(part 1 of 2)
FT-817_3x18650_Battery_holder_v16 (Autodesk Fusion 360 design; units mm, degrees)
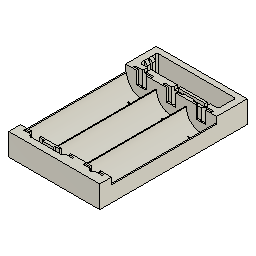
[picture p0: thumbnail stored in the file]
parameter "d153" = 1.5
parameter "d175" = 1.8
parameter "d203" = 3.15
parameter "d205" = 3
sketch "Sketch2" plane through (0, 0, 0) normal (0, 0, 1) x axis (1, 0, 0)
  line L1 (29, 41) -> (-29, 41)
  line L2 (29, -41) -> (29, 41)
  line L3 (-29, -41) -> (29, -41)
  line L4 (-29, 41) -> (-29, -41)
  line L5 (29, 53) -> (29, 41)
  line L6 (-29, 53) -> (29, 53)
  line L7 (-29, 41) -> (-29, 53)
  line L8 (0, -45) -> (0, 0)
  line L9 (-33, 0) -> (0, 0)
  point P1 (0, 0)
  point P8 (0, 0)
  point P10 (0, 0)
  point P4 (29, -41)
  point P6 (29, 53)
  point P5 (-29, -41)
  horizontal L1
  vertical L2
  horizontal L3
  vertical L4
  perpendicular L1 L5
  perpendicular L5 L6
  perpendicular L1 L7
  coincident P1 P8
  vertical L8
  coincident P1 P10
  perpendicular L4 L9
  symmetric L2 L4 L8
  symmetric L1 L3 L9
  dimension "d9" distance P4 P6 = 94
  dimension "d10" distance P4 P5 = 58
  dimension "d27" distance L3 L9 = 41
extrude "Extrude2" new body sketch "Sketch2" profile of L1 L2 L3 L4 L5 L6 L7 along normal blind 14.2
sketch "18650" plane through (0, 0, 0) normal (0, 1, 0) x axis (1, 0, 0)
  line L1 (0, -22) -> (0, 0)
  line L2 (56, -0.2) -> (-41, -0.2)
  line L3 (85, 0) -> (0, 0)
  line L4 (-9.75, -26.6294) -> (-9.75, 2.3706)
  line L5 (-9.25, -26.6294) -> (-9.25, 1.9073)
  line L6 (9.25, -26) -> (9.25, 2)
  line L7 (9.75, -25.722) -> (9.75, 2.278)
  circle C1 centre (0, -9.45) radius 9.25
  circle C2 centre (19, -9.45) radius 9.25
  circle C3 centre (-19, -9.45) radius 9.25
  point P1 (0, 0)
  point P2 (0, 0)
  point P4 (0, -9.45)
  point P7 (0, 0)
  coincident P1 P2
  vertical L1
  coincident L1 P4
  horizontal L2
  tangent C1 L2
  coincident P1 P7
  perpendicular L1 L3
  tangent L2 C2
  tangent L2 C3
  perpendicular L2 L4
  perpendicular L2 L5
  tangent C3 L4
  tangent C1 L5
  perpendicular L2 L6
  perpendicular L3 L7
  tangent C2 L7
  tangent C1 L6
  dimension "d1" diameter C1 = 18.5
  dimension "d2" distance L2 L3 = 0.2
  dimension "d3" diameter C2 = 18.5 (= "d1")
  dimension "d4" diameter C3 = 18.5 (= "d1")
  dimension "d5" distance L6 L7 = 0.5
  dimension "d6" distance L4 L5 = 0.5 (= "d5")
extrude "Extrude1" new body sketch "18650" profile of C1 C2 C3 distance 67 (= "70 mm - 3 mm") named "d7"
copy_paste_bodies "CopyPasteBodies1"
combine "Combine1"
sketch "Sketch3" plane through (-29, 0, 0) normal (-1, 0, 0) x axis (0, -1, 0)
  line L1 (41, 0) -> (-53, 0)
  line L2 (41, 14.2) -> (41, 0)
  line L3 (-53, 14.2) -> (41, 14.2)
  line L4 (-53, 0) -> (-53, 14.2)
  line L5 (-33.5, 10) -> (-33.5, 14.2)
  line L6 (33.5, 10) -> (-33.5, 10)
  line L7 (33.5, 14.2) -> (33.5, 10)
  line L8 (0, 23) -> (0, 0)
  line L9 (33.25, 14.2) -> (33.25, 10)
  point P6 (-33.5, 14.2)
  point P9 (33.5, 14.2)
  point P1 (0, 0)
  point P10 (0, 0)
  point P7 (-33.5, 10)
  point P8 (33.5, 10)
  coincident L3 P6
  perpendicular L3 L5
  perpendicular L5 L6
  coincident L3 P9
  perpendicular L3 L7
  coincident P1 P10
  perpendicular L6 L8
  symmetric L5 L7 L8
  dimension "d13" distance P6 P7 = 4.2
  dimension "d14" distance P7 P8 = 67 (= "d7")
  dimension "d18" = -0.25
sketch "Sketch4" plane through (0, 0, 14.2) normal (0, 0, 1) x axis (-1, 0, 0)
  line L1 (-29, -53) -> (-29, 41)
  line L2 (29, -53) -> (-29, -53)
  line L3 (29, 41) -> (29, -53)
  line L4 (-29, 41) -> (29, 41)
  line L5 (28.25, 0) -> (9.75, 0)
  line L6 (9.25, 0) -> (-9.25, 0)
  line L7 (-9.75, 0) -> (-28.25, 0)
  line L8 (19, -61.033) -> (19, 41.4982)
  line L9 (0, -61.033) -> (0, 41.8886)
  line L10 (-19, -60.5882) -> (-19, 42.3334)
  line L11 (-11.0627, 33.5) -> (-26.9373, 33.5)
  line L12 (-11.0627, -33.5) -> (-11.0627, 33.5)
  line L13 (-26.9373, -33.5) -> (-11.0627, -33.5)
  line L14 (-26.9373, 33.5) -> (-26.9373, -33.5)
  line L15 (7.9373, 33.5) -> (-7.9373, 33.5)
  line L16 (7.9373, -33.5) -> (7.9373, 33.5)
  line L17 (-7.9373, -33.5) -> (7.9373, -33.5)
  line L18 (-7.9373, 33.5) -> (-7.9373, -33.5)
  line L19 (26.9373, 33.5) -> (11.0627, 33.5)
  line L20 (26.9373, -33.5) -> (26.9373, 33.5)
  line L21 (11.0627, -33.5) -> (26.9373, -33.5)
  line L22 (11.0627, 33.5) -> (11.0627, -33.5)
  line L23 (6, 34.5) -> (-6, 34.5)
  line L24 (6, 35.5) -> (6, 34.5)
  line L25 (-6, 35.5) -> (6, 35.5)
  line L26 (-6, 34.5) -> (-6, 35.5)
  line L27 (3, 34.5) -> (3, 33.5)
  line L28 (-3, 34.5) -> (-3, 33.5)
  line L29 (-25, -44.6) -> (25, -44.6)
  line L30 (-25, -43.5) -> (-25, -44.6)
  line L31 (25, -43.5) -> (-25, -43.5)
  line L32 (25, -44.6) -> (25, -43.5)
  line L33 (-41.708, 0) -> (39.9599, 0)
  line L34 (-6, -35.5) -> (6, -35.5)
  line L35 (6, -35.5) -> (6, -34.5)
  line L36 (6, -34.5) -> (-6, -34.5)
  line L37 (-6, -34.5) -> (-6, -35.5)
  line L38 (-3, -34.5) -> (-3, -33.5)
  line L39 (3, -34.5) -> (3, -33.5)
  line L40 (-36.2069, -28.9904) -> (34.2527, -28.9904)
  line L41 (33.3168, 27.6224) -> (-72.3156, 27.6224)
  curve K1 (-16.2649, -28.9904) -> (-20.9089, -28.9904)
  curve K2 (-16.2649, -20.9904) -> (-16.2649, -28.9904)
  curve K3 (-20.9089, -20.9904) -> (-16.2649, -20.9904)
  curve K4 (-20.9089, -28.9904) -> (-20.9089, -20.9904)
  curve K5 (21.8796, -28.9904) -> (17.1621, -28.9904)
  curve K6 (21.8796, -20.9904) -> (21.8796, -28.9904)
  curve K7 (17.1621, -20.9904) -> (21.8796, -20.9904)
  curve K8 (17.1621, -28.9904) -> (17.1621, -20.9904)
  curve K9 (1.9562, -28.9904) -> (-0.9401, -28.9904)
  curve K10 (1.9562, -20.9904) -> (1.9562, -28.9904)
  curve K11 (-0.9401, -20.9904) -> (1.9562, -20.9904)
  curve K12 (-0.9401, -28.9904) -> (-0.9401, -20.9904)
  curve K13 (-3.5054, 27.6056) -> (1.7961, 27.6224)
  curve K14 (-3.48, 19.6057) -> (-3.5054, 27.6056)
  curve K15 (1.8215, 19.6225) -> (-3.48, 19.6057)
  curve K16 (1.7961, 27.6224) -> (1.8215, 19.6225)
  curve K17 (-22.211, 27.6224) -> (-18.0311, 27.6224)
  curve K18 (-22.211, 19.6224) -> (-22.211, 27.6224)
  curve K19 (-18.0311, 19.6224) -> (-22.211, 19.6224)
  curve K20 (-18.0311, 27.6224) -> (-18.0311, 19.6224)
  curve K21 (17.5387, 27.6188) -> (20.2052, 27.6224)
  curve K22 (17.5495, 19.6188) -> (17.5387, 27.6188)
  curve K23 (20.2161, 19.6224) -> (17.5495, 19.6188)
  curve K24 (20.2052, 27.6224) -> (20.2161, 19.6224)
  line L42 (25, -41.5) -> (-25, -41.5)
  line L43 (-25, -46.6) -> (25, -46.6)
  line L44 (23, -41.5) -> (23, -43.5)
  line L45 (23, -46.6) -> (23, -44.6)
  line L46 (-23, -41.5) -> (-23, -43.5)
  line L47 (-23, -44.6) -> (-23, -46.6)
  line L48 (-25, -49.6) -> (-25, -46.6)
  line L49 (25, -49.6) -> (-25, -49.6)
  line L50 (25, -49.6) -> (25, -46.6)
  line L51 (25, -38.5) -> (25, -41.5)
  line L52 (-25, -38.5) -> (25, -38.5)
  line L53 (-25, -41.5) -> (-25, -38.5)
  line L54 (12.5, -43.5) -> (12.5, -44.6)
  line L55 (23, -44.6) -> (23, -43.5)
  line L56 (-23, -44.6) -> (-23, -43.5)
  line L57 (14.3714, -49.6) -> (14.3714, -38.5)
  line L58 (10.6286, -49.6) -> (10.6286, -38.5)
  line L59 (-14.3714, -49.6) -> (-14.3714, -38.5)
  line L60 (-10.6286, -49.6) -> (-10.6286, -38.5)
  line L61 (-13, 34.5) -> (-25, 34.5)
  line L62 (-16, 34.5) -> (-16, 33.5)
  line L63 (-22, 34.5) -> (-22, 33.5)
  line L64 (-25, 34.5) -> (-25, 35.5)
  line L65 (-25, 35.5) -> (-13, 35.5)
  line L66 (-13, 35.5) -> (-13, 34.5)
  line L67 (-13, -34.5) -> (-25, -34.5)
  line L68 (-25, -35.5) -> (-13, -35.5)
  line L69 (-16, -34.5) -> (-16, -33.5)
  line L70 (-22, -34.5) -> (-22, -33.5)
  line L71 (-25, -34.5) -> (-25, -35.5)
  line L72 (-13, -35.5) -> (-13, -34.5)
  line L73 (25, 34.5) -> (13, 34.5)
  line L74 (22, 34.5) -> (22, 33.5)
  line L75 (16, 34.5) -> (16, 33.5)
  line L76 (13, 34.5) -> (13, 35.5)
  line L77 (13, 35.5) -> (25, 35.5)
  line L78 (25, 35.5) -> (25, 34.5)
  line L79 (25, -34.5) -> (13, -34.5)
  line L80 (13, -35.5) -> (25, -35.5)
  line L81 (22, -34.5) -> (22, -33.5)
  line L82 (16, -34.5) -> (16, -33.5)
  line L83 (13, -34.5) -> (13, -35.5)
  line L84 (25, -35.5) -> (25, -34.5)
  line L85 (0, 37) -> (19, 37)
  line L86 (-19, -37) -> (0, -37)
  line L87 (6, 35.5) -> (13, 35.5)
  line L88 (-13, -35.5) -> (-6, -35.5)
  line L89 (20, -38.5) -> (20, -36.618)
  line L90 (18, -38.5) -> (18, -36.618)
  line L91 (1, -38.5) -> (1, -36.618)
  line L92 (-1, -38.5) -> (-1, -36.618)
  line L93 (-18, -38.5) -> (-18, -36.618)
  line L94 (-20, -38.5) -> (-20, -36.618)
  circle C1 centre (0, 35.5) radius 1.5
  circle C2 centre (0, -35.5) radius 1.5
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  point P18 (19, 0)
  point P19 (0, 0)
  point P20 (-19, 0)
  point P37 (3, 33.5)
  point P38 (3, 34.5)
  point P39 (-3, 33.5)
  point P40 (-3, 34.5)
  point P41 (0, 35.5)
  point P1 (0, 0)
  point P33 (-6, 34.5)
  point P51 (-6, -34.5)
  point P34 (6, 34.5)
  point P50 (6, -34.5)
  point P35 (6, 35.5)
  point P48 (6, -35.5)
  point P36 (-6, 35.5)
  point P49 (-6, -35.5)
  point P54 (3, -33.5)
  point P55 (3, -34.5)
  point P52 (-3, -33.5)
  point P53 (-3, -34.5)
  point P61 (-20.9089, -28.9904)
  point P65 (17.1621, -28.9904)
  point P69 (-0.9401, -28.9904)
  point P73 (1.7961, 27.6224)
  point P83 (20.2052, 27.6224)
  point P77 (-18.0311, 27.6224)
  point P89 (23, -43.5)
  point P90 (23, -41.5)
  point P91 (23, -44.6)
  point P92 (23, -46.6)
  point P93 (-23, -43.5)
  point P94 (-23, -41.5)
  point P95 (-23, -46.6)
  point P96 (-23, -44.6)
  point P98 (25, -49.6)
  point P99 (25, -49.6)
  point P102 (12.5, -44.6)
  point P103 (12.5, -43.5)
  point P104 (14.3714, -38.5)
  point P108 (-14.3714, -38.5)
  point P105 (14.3714, -49.6)
  point P109 (-14.3714, -49.6)
  point P106 (10.6286, -38.5)
  point P110 (-10.6286, -38.5)
  point P107 (10.6286, -49.6)
  point P111 (-10.6286, -49.6)
  point P148 (19, 37)
  point P149 (0, 37)
  point P150 (0, -37)
  point P151 (-19, -37)
  point P153 (20, -38.5)
  point P155 (18, -38.5)
  point P156 (1, -36.618)
  point P157 (1, -38.5)
  point P158 (-1, -36.618)
  point P159 (-1, -38.5)
  point P161 (-18, -38.5)
  point P163 (-20, -38.5)
  point P42 (25, -44.6)
  point P43 (-25, -44.6)
  point P45 (25, -43.5)
  point P74 (-3.5054, 27.6056)
  point P75 (-3.48, 19.6057)
  point P66 (21.8796, -28.9904)
  point P67 (21.8796, -20.9904)
  point P62 (-16.2649, -28.9904)
  point P63 (-16.2649, -20.9904)
  point P72 (-0.9401, -20.9904)
  point P81 (20.2161, 19.6224)
  point P80 (-18.0311, 19.6224)
  point P44 (-25, -43.5)
  point P88 (-25, -46.6)
  point P97 (-25, -49.6)
  point P86 (25, -41.5)
  point P100 (25, -38.5)
  point P56 (0, -35.5)
  perpendicular L2 L8
  perpendicular L2 L9
  perpendicular L2 L10
  coincident L8 P18
  coincident L9 P19
  coincident L10 P20
  horizontal L23
  vertical L24
  horizontal L25
  vertical L26
  symmetric L9 L24 L26
  coincident L15 P37
  coincident L23 P38
  perpendicular L23 L27
  coincident L15 P39
  coincident L23 P40
  perpendicular L23 L28
  coincident L9 P41
  horizontal L29
  vertical L30
  horizontal L31
  vertical L32
  symmetric L9 L30 L32
  perpendicular L14 L33
  coincident P1 L33
  symmetric P33 L33 P51
  symmetric P34 L33 P50
  symmetric P35 L33 P48
  symmetric P36 L33 P49
  symmetric P37 L33 P54
  symmetric P38 L33 P55
  symmetric P39 L33 P52
  symmetric P40 L33 P53
  symmetric C1 L33 C2
  perpendicular K1 K2
  parallel K1 K3
  parallel K2 K4
  coincident L40 P61
  perpendicular K5 K6
  parallel K5 K7
  parallel K6 K8
  coincident L40 P65
  perpendicular K9 K10
  parallel K9 K11
  parallel K10 K12
  coincident L40 P69
  horizontal L41
  perpendicular K13 K14
  parallel K13 K15
  parallel K14 K16
  coincident L41 P73
  vertical K6
  vertical K10
  vertical K2
  horizontal L40
  perpendicular K17 K18
  parallel K17 K19
  parallel K18 K20
  perpendicular K21 K22
  parallel K21 K23
  parallel K22 K24
  coincident L41 P83
  coincident L41 P77
  coincident L31 P89
  coincident L42 P90
  perpendicular L42 L44
  coincident L29 P91
  coincident L43 P92
  perpendicular L43 L45
  coincident L31 P93
  coincident L42 P94
  perpendicular L42 L46
  coincident L43 P95
  coincident L29 P96
  perpendicular L29 L47
  perpendicular L43 L48
  perpendicular L48 L49
  perpendicular L43 L50
  coincident P98 P99
  perpendicular L42 L51
  perpendicular L10 L52
  perpendicular L42 L53
  coincident L29 P102
  coincident L31 P103
  perpendicular L31 L54
  perpendicular L43 L57
  perpendicular L43 L58
  symmetric L54 L57 L58
  symmetric L9 P104 P108
  symmetric L9 P105 P109
  symmetric L9 P106 P110
  symmetric L9 P107 P111
  coincident L52 P104
  coincident L49 P105
  coincident L49 P107
  coincident L52 P106
  coincident L25 P41
  coincident L8 P148
  coincident L9 P149
  coincident C1 P149
  coincident C2 P150
  coincident L9 P150
  coincident L10 P151
  coincident L52 P153
  perpendicular L52 L89
  coincident L52 P155
  perpendicular L52 L90
  coincident C2 P156
  coincident L52 P157
  perpendicular L52 L91
  coincident C2 P158
  coincident L52 P159
  perpendicular L52 L92
  coincident L52 P161
  perpendicular L52 L93
  coincident L52 P163
  perpendicular L52 L94
  symmetric L10 L93 L94
  dimension "d19" distance P33 P34 = 12
  dimension "d20" distance P33 P36 = 1
  dimension "d21" distance L27 L28 = 6
  dimension "d22" distance P37 P38 = 1
  dimension "d23" diameter C1 = 3
  dimension "d25" distance P42 P43 = 50
  dimension "d26" distance P42 P45 = 1.1
  dimension "d42" distance P74 P75 = 8
  dimension "d43" distance P66 P67 = 8 (= "d42")
  dimension "d44" distance P62 P63 = 8 (= "d42")
  dimension "d45" distance P69 P72 = 8 (= "d42")
  dimension "d46" distance P81 P83 = 8 (= "d42")
  dimension "d47" distance P77 P80 = 8 (= "d42")
  dimension "d52" = -2
  dimension "d53" = -2
  dimension "d54" distance P42 P91 = 2
  dimension "d55" distance P45 P89 = 2 (= "d54")
  dimension "d56" distance P43 P96 = 2 (= "d54")
  dimension "d57" distance P44 P93 = 2 (= "d54")
  dimension "d58" distance P88 P97 = 3
  dimension "d59" distance P86 P100 = 3
  dimension "d61" distance P56 L52 = 3
  dimension "d63" distance L9 L54 = 12.5 (= "( d25 / 2 ) / 2")
  dimension "d85" distance L89 L90 = 2
  dimension "d86" distance L91 L92 = 2 (= "d85")
  dimension "d87" distance L93 L94 = 2 (= "d85")
  dimension "d70" R-Pattern1-uDistance = -19 (= "-( d1 + d5 )")
  dimension "d71" R-Pattern1-vDistance = -20
extrude "Extrude3" cut sketch "Sketch3" profile of L3 L5 L6 L7 L9 to an object
extrude "Extrude4" cut sketch "Sketch4" to an object
extrude "Extrude5" cut sketch "Sketch4" profile of L11 L13 L15 L17 L19 L21 L23 L27 L28 C1 L36 L38 L39 C2 against normal blind 8
extrude "Extrude6" cut sketch "Sketch4" against normal blind 12
extrude "Extrude8" cut sketch "Sketch4" to an object offset 0.1
extrude "Extrude9" cut sketch "Sketch4" profile of L29 L30 L31 L32 L42 L43 L44 L45 L46 L47 L48 L49 L50 L51 L52 L53 to an object offset -0.2
extrude "Extrude10" cut sketch "Sketch4" profile of L29 L31 L42 L43 L44 L45 L46 L47 L48 L49 L50 L51 L52 L53 L55 L56 L57 L58 L59 L60 to an object
sketch "test" plane through (0, 0, 14.2) normal (0, 0, 1) x axis (-1, 0, 0)
  line L1 (17.5, 35.5) -> (13, 35.5)
  line L2 (25, 35.5) -> (20.5, 35.5)
  line L3 (25, 34.5) -> (25, 35.5)
  line L4 (22, 34.5) -> (25, 34.5)
  line L5 (22, 33.5) -> (22, 34.5)
  line L6 (29, 33.5) -> (22, 33.5)
  line L7 (29, 41) -> (29, 33.5)
  line L8 (-29, 41) -> (29, 41)
  line L9 (-29, 33.5) -> (-29, 41)
  line L10 (-22, 33.5) -> (-29, 33.5)
  line L11 (-22, 34.5) -> (-22, 33.5)
  line L12 (-25, 34.5) -> (-22, 34.5)
  line L13 (-25, 35.5) -> (-25, 34.5)
  line L14 (-20.5, 35.5) -> (-25, 35.5)
  line L15 (-13, 35.5) -> (-17.5, 35.5)
  line L16 (-13, 34.5) -> (-13, 35.5)
  line L17 (-16, 34.5) -> (-13, 34.5)
  line L18 (-16, 33.5) -> (-16, 34.5)
  line L19 (-3, 33.5) -> (-16, 33.5)
  line L20 (-3, 34.5) -> (-3, 33.5)
  line L21 (-6, 34.5) -> (-3, 34.5)
  line L22 (-6, 35.5) -> (-6, 34.5)
  line L23 (-1.5, 35.5) -> (-6, 35.5)
  line L24 (6, 35.5) -> (1.5, 35.5)
  line L25 (6, 34.5) -> (6, 35.5)
  line L26 (3, 34.5) -> (6, 34.5)
  line L27 (3, 33.5) -> (3, 34.5)
  line L28 (16, 33.5) -> (3, 33.5)
  line L29 (16, 34.5) -> (16, 33.5)
  line L30 (13, 34.5) -> (16, 34.5)
  line L31 (13, 35.5) -> (13, 34.5)
  line L32 (-28.119, 32.915) -> (-10.2958, 32.915)
  line L33 (-28.119, 39.6674) -> (-28.119, 32.915)
  line L34 (-10.2958, 39.6674) -> (-28.119, 39.6674)
  line L35 (-10.2958, 32.915) -> (-10.2958, 39.6674)
  arc A1 centre (19, 35.5) radius 1.5 clockwise from (17.5, 35.5) to (20.5, 35.5)
  arc A2 centre (-19, 35.5) radius 1.5 clockwise from (-20.5, 35.5) to (-17.5, 35.5)
  arc A3 centre (0, 35.5) radius 1.5 clockwise from (-1.5, 35.5) to (1.5, 35.5)
  horizontal L32
  vertical L33
  horizontal L34
  vertical L35
sketch "Sketch5" plane through (0, 0, 0) normal (0, 0, -1) x axis (1, 0, 0)
  line L1 (29, 41) -> (29, -53)
  line L2 (-29, 41) -> (29, 41)
  line L3 (-29, -53) -> (-29, 41)
  line L4 (29, -53) -> (-29, -53)
  line L5 (-1.299, -36.25) -> (-17.701, -36.25)
  line L6 (-17.701, -30.1088) -> (-17.701, -41.5945)
  line L7 (-1.299, -29.2291) -> (-1.299, -41.7493)
  line L8 (50.6132, 0) -> (-40.9094, 0)
  line L9 (0, 47.5994) -> (0, -56.3042)
  line L10 (-10.25, 0) -> (-10.25, -34.75)
  line L11 (-8.75, 0) -> (-8.75, -34.75)
  line L12 (-9.5, 0) -> (-9.5, -36.25)
  line L13 (-10.25, -34.75) -> (-17.701, -34.75)
  line L14 (-1.299, -34.75) -> (-8.75, -34.75)
  line L15 (10.25, 0) -> (10.25, -34.75)
  line L16 (8.75, 0) -> (8.75, -34.75)
  line L17 (10.25, -34.75) -> (17.701, -34.75)
  line L18 (1.299, -36.25) -> (17.701, -36.25)
  line L19 (1.299, -34.75) -> (8.75, -34.75)
  line L20 (-10.25, 0) -> (-10.25, 34.75)
  line L21 (-8.75, 0) -> (-8.75, 34.75)
  line L22 (-10.25, 34.75) -> (-17.701, 34.75)
  line L23 (-1.299, 36.25) -> (-17.701, 36.25)
  line L24 (-1.299, 34.75) -> (-8.75, 34.75)
  line L25 (1.299, 34.75) -> (8.75, 34.75)
  line L26 (1.299, 36.25) -> (17.701, 36.25)
  line L27 (10.25, 34.75) -> (17.701, 34.75)
  line L28 (10.25, 0) -> (10.25, 34.75)
  line L29 (8.75, 0) -> (8.75, 34.75)
  line L30 (14.3714, -49.6) -> (25, -49.6)
  line L31 (14.3714, -38.5) -> (14.3714, -49.6)
  line L32 (25, -38.5) -> (14.3714, -38.5)
  line L33 (25, -41.5) -> (25, -38.5)
  line L34 (23, -41.5) -> (25, -41.5)
  line L35 (23, -46.6) -> (23, -41.5)
  line L36 (25, -46.6) -> (23, -46.6)
  line L37 (25, -49.6) -> (25, -46.6)
  line L38 (-25, -49.6) -> (-14.3714, -49.6)
  line L39 (-25, -46.6) -> (-25, -49.6)
  line L40 (-23, -46.6) -> (-25, -46.6)
  line L41 (-23, -41.5) -> (-23, -46.6)
  line L42 (-25, -41.5) -> (-23, -41.5)
  line L43 (-25, -38.5) -> (-25, -41.5)
  line L44 (-14.3714, -38.5) -> (-25, -38.5)
  line L45 (-14.3714, -49.6) -> (-14.3714, -38.5)
  line L46 (-10.6286, -38.5) -> (-10.6286, -49.6)
  line L47 (10.6286, -38.5) -> (-10.6286, -38.5)
  line L48 (10.6286, -49.6) -> (10.6286, -38.5)
  line L49 (-10.6286, -49.6) -> (10.6286, -49.6)
  circle C1 centre (0, 35.5) radius 1.5
  circle C2 centre (0, -35.5) radius 1.5
  circle C3 centre (-19, 35.5) radius 1.5
  circle C4 centre (19, -35.5) radius 1.5
  circle C5 centre (19, 35.5) radius 1.5
  circle C6 centre (-19, -35.5) radius 1.5
  point P9 (-1.299, -34.75)
  point P11 (-1.299, -36.25)
  point P8 (-17.701, -34.75)
  point P10 (-17.701, -36.25)
  point P1 (0, 0)
  point P21 (-10.25, 0)
  point P22 (-8.75, -34.75)
  point P25 (-9.5, 0)
  point P24 (-9.5, -36.25)
  point P30 (17.701, -34.75)
  point P33 (1.299, -34.75)
  point P31 (17.701, -36.25)
  point P32 (1.299, -36.25)
  point P20 (-10.25, -34.75)
  point P26 (10.25, -34.75)
  point P27 (10.25, 0)
  point P28 (8.75, -34.75)
  point P23 (-8.75, 0)
  point P29 (8.75, 0)
  point P38 (-17.701, 34.75)
  point P41 (-1.299, 34.75)
  point P39 (-17.701, 36.25)
  point P40 (-1.299, 36.25)
  point P34 (-10.25, 34.75)
  point P35 (-10.25, 0)
  point P36 (-8.75, 34.75)
  point P37 (-8.75, 0)
  point P47 (10.25, 34.75)
  point P48 (10.25, 0)
  point P42 (8.75, 34.75)
  point P49 (8.75, 0)
  point P46 (17.701, 34.75)
  point P44 (17.701, 36.25)
  point P45 (1.299, 36.25)
  point P43 (1.299, 34.75)
  coincident C2 P9
  horizontal L13
  coincident C2 P11
  parallel L5 L13
  perpendicular L5 L6
  coincident P9 L7
  coincident P11 L7
  coincident P8 L6
  coincident P10 L6
  perpendicular L3 L8
  perpendicular L2 L9
  coincident P1 L8
  coincident P1 L9
  coincident L8 P21
  perpendicular L8 L10
  coincident P22 L13
  perpendicular L11 L13
  coincident L8 P25
  perpendicular L8 L12
  symmetric L10 L11 L12
  collinear L13 L14
  midpoint L5 P24
  symmetric P8 L9 P30
  symmetric P9 L9 P33
  symmetric P10 L9 P31
  symmetric P11 L9 P32
  symmetric L9 P20 P26
  symmetric L9 P21 P27
  symmetric L9 P22 P28
  symmetric L9 P23 P29
  symmetric P8 L8 P38
  symmetric P9 L8 P41
  symmetric P10 L8 P39
  symmetric P11 L8 P40
  symmetric L8 P20 P34
  symmetric L8 P21 P35
  symmetric L8 P22 P36
  symmetric L8 P23 P37
  symmetric L8 P26 P47
  symmetric L8 P27 P48
  symmetric L8 P28 P42
  symmetric L8 P29 P49
  symmetric L8 P30 P46
  symmetric L8 P31 P44
  symmetric L8 P32 P45
  symmetric L8 P33 P43
  vertical L7
  coincident P8 C6
  dimension "d38" distance L5 L13 = 1.5
  dimension "d39" distance L10 L11 = 1.5
extrude "Extrude11" cut sketch "Sketch5" profile of C1 C2 L14 L5 L10 L11 L15 L16 L17 L18 L19 L20 L21 L22 L23 L24 L25 L26 L27 L28 L29 C3 C4 C5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 against normal blind 1.8
sketch "Sketch7" plane through (0, 53, 0) normal (0, 1, 0) x axis (-1, 0, 0)
  line L1 (29, 0) -> (-29, 0)
  line L2 (29, 14.2) -> (29, 0)
  line L3 (-29, 14.2) -> (29, 14.2)
  line L4 (-29, 0) -> (-29, 14.2)
  circle C1 centre (-21, 5) radius 1.25
  point P6 (-21, 5)
  dimension "d75" diameter C1 = 2.5
  dimension "d76" distance L1 P6 = 5
  dimension "d77" distance L4 P6 = 8
extrude "Extrude12" cut sketch "Sketch7" profile of C1 to an object
chamfer "Chamfer1" distance 2
chamfer "Chamfer2" distance 1
extrude "Extrude13" cut sketch "Sketch4" against normal blind 2
extrude "Extrude14" add of existing geometry blind 1
sketch "Sketch1" plane through (0, 0, 0) normal (0, 1, 0) x axis (1, 0, 0)
  line L1 (6.1, 0) -> (-6.1, 0)
  line L2 (6.1, -12.2) -> (6.1, 0)
  line L3 (-6.1, -12.2) -> (6.1, -12.2)
  line L4 (-6.1, 0) -> (-6.1, -12.2)
  line L5 (0, 11.5199) -> (0, -14.3743)
  line L6 (-1.55, 7) -> (-1.55, 0)
  line L7 (1.55, 7) -> (1.55, 0)
  line L8 (9.7687, -10.2) -> (-9.2383, -10.2)
  arc A1 centre (0, 7) radius 1.55 clockwise from (-1.55, 7) to (1.55, 7)
  circle C1 centre (0, 7) radius 1
  circle C2 centre (0, -6.7) radius 3.5
  point P8 (-1.55, 0)
  point P10 (1.55, 0)
  point P1 (0, 0)
  point P14 (0, -6.7)
  point P2 (-6.1, 0)
  point P3 (6.1, 0)
  point P5 (-6.1, -12.2)
  point P9 (-1.55, 7)
  horizontal L1
  vertical L2
  horizontal L3
  vertical L4
  perpendicular L1 L5
  coincident L1 P8
  perpendicular L1 L6
  coincident L1 P10
  perpendicular L1 L7
  equal L6 L7
  symmetric L5 L6 L7
  tangent L6 A1
  concentric A1 C1
  coincident P1 L5
  coincident L5 P14
  coincident P1 L1
  symmetric L2 L4 L5
  perpendicular L5 L8
  tangent C2 L8
  dimension "d90" distance P2 P3 = 12.2
  dimension "d91" distance P2 P5 = 12.2
  dimension "d92" distance P8 P9 = 7
  dimension "d93" distance L6 L7 = 3.1
  dimension "d94" diameter C1 = 2
  dimension "d95" diameter C2 = 7
  dimension "d96" distance L3 L8 = 2
extrude "Extrude1" new body sketch "Sketch1" profile of L1 L2 L3 L4 L6 L7 A1 C1 C2 along normal blind 0.4
extrude "Extrude2" add sketch "Sketch1" profile of C2 along normal blind 2
fillet "Fillet1" radius 2
sketch "Sketch1" plane through (0, 0, 0) normal (0, 1, 0) x axis (1, 0, 0)
  line L1 (6.1, 0) -> (-6.1, 0)
  line L2 (6.1, -12.2) -> (6.1, 0)
  line L3 (-6.1, -12.2) -> (6.1, -12.2)
  line L4 (-6.1, 0) -> (-6.1, -12.2)
  line L5 (0, 11.5199) -> (0, -14.3743)
  line L6 (-1.55, 7) -> (-1.55, 0)
  line L7 (1.55, 7) -> (1.55, 0)
  line L8 (9.7687, -8.7) -> (-9.2383, -8.7)
  arc A1 centre (0, 7) radius 1.55 clockwise from (-1.55, 7) to (1.55, 7)
  circle C1 centre (0, 7) radius 1
  circle C2 centre (0, -7.45) radius 1.25
  point P8 (-1.55, 0)
  point P10 (1.55, 0)
  point P1 (0, 0)
  point P14 (0, -7.45)
  point P2 (-6.1, 0)
  point P3 (6.1, 0)
  point P5 (-6.1, -12.2)
  point P9 (-1.55, 7)
  horizontal L1
  vertical L2
  horizontal L3
  vertical L4
  perpendicular L1 L5
  coincident L1 P8
  perpendicular L1 L6
  coincident L1 P10
  perpendicular L1 L7
  equal L6 L7
  symmetric L5 L6 L7
  tangent L6 A1
  concentric A1 C1
  coincident P1 L5
  coincident L5 P14
  coincident P1 L1
  symmetric L2 L4 L5
  perpendicular L5 L8
  tangent C2 L8
  dimension "d90_1" distance P2 P3 = 12.2
  dimension "d91_1" distance P2 P5 = 12.2
  dimension "d92_1" distance P8 P9 = 7
  dimension "d93_1" distance L6 L7 = 3.1
  dimension "d94_1" diameter C1 = 2
  dimension "d95_1" diameter C2 = 2.5
  dimension "d96_1" distance L3 L8 = 3.5
extrude "Extrude1" new body sketch "Sketch1" profile of L1 L2 L3 L4 L6 L7 A1 C1 C2 along normal blind 0.4 named "d97_1"
coil_primitive "CoilPrimitive2" Diameter 5 SectionSize 0.5 TaperAngle 0 Height 10
base_mesh_feature "Base Mesh Feature1"
sketch "Sketch1" plane through (0, 0, 0) normal (0, 0, 1) x axis (1, 0, 0)
  line L1 (31.3495, 49) -> (-33.3005, 49)
  line L2 (31.3495, -49) -> (31.3495, 49)
  line L3 (-33.3005, -49) -> (31.3495, -49)
  line L4 (-33.3005, 49) -> (-33.3005, -49)
  line L5 (0, 55.7908) -> (0, 0)
  line L6 (49.8312, 0) -> (0, 0)
  line L7 (27.3495, 46) -> (-29.3005, 46)
  line L8 (27.3495, -46) -> (27.3495, 46)
  line L9 (-29.3005, -46) -> (27.3495, -46)
  line L10 (-29.3005, 46) -> (-29.3005, -46)
  arc A1 centre (31.9995, 0) radius 2.5831 clockwise from (31.3495, -2.5) to (31.3495, 2.5)
  point P1 (0, 0)
  point P6 (0, 0)
  point P8 (0, 0)
  point P11 (31.3495, -2.5)
  point P10 (31.3495, 2.5)
  point P12 (31.9995, 0)
  point P2 (-33.3005, 49)
  point P3 (31.3495, 49)
  horizontal L1
  vertical L2
  horizontal L3
  vertical L4
  coincident P1 P6
  perpendicular L1 L5
  coincident P1 P8
  perpendicular L5 L6
  symmetric L1 L3 L6
  coincident L2 P11
  coincident L2 P10
  symmetric L6 P10 P11
  horizontal L7
  vertical L8
  horizontal L9
  vertical L10
  dimension "d114" distance L1 L3 = 98
  dimension "d115" distance P10 P11 = 5
  dimension "d116" distance L2 P12 = 0.65
  dimension "d117" distance L1 L7 = 3
  dimension "d118" distance L3 L9 = 3 (= "d117")
  dimension "d119" distance L2 L8 = 4
  dimension "d120" distance L4 L10 = 4
  dimension "d198" distance P2 P3 = 64.65
extrude "Extrude1" new body sketch "Sketch1" profile of L1 L2 L3 L4 A1 L7 L8 L9 L10 along normal blind 1
sketch "Sketch2" plane through (0, 0, 1) normal (0, 0, 1) x axis (-1, 0, 0)
  line L1 (29.3005, 46) -> (-27.3495, 46)
  line L2 (29.3005, -46) -> (29.3005, 46)
  line L3 (-27.3495, -46) -> (29.3005, -46)
  line L4 (-27.3495, 46) -> (-27.3495, -46)
  line L5 (-31.3495, -49) -> (-31.3495, -2.5)
  line L6 (33.3005, -49) -> (-31.3495, -49)
  line L7 (33.3005, 49) -> (33.3005, -49)
  line L8 (-31.3495, 49) -> (33.3005, 49)
  line L9 (-31.3495, 2.5) -> (-31.3495, 49)
  line L10 (-28.7495, -47) -> (32.3005, -47)
  line L11 (-28.7495, 47) -> (-28.7495, -47)
  line L12 (32.3005, 47) -> (-28.7495, 47)
  line L13 (32.3005, -47) -> (32.3005, 47)
  line L14 (-27.3495, 46) -> (-27.3495, -46)
  line L15 (29.3005, 46) -> (-27.3495, 46)
  line L16 (29.3005, -46) -> (29.3005, 46)
  line L17 (-27.3495, -46) -> (29.3005, -46)
  line L18 (-27.3495, 20) -> (-28.7495, 20)
  line L19 (-27.3495, 45) -> (-28.7495, 45)
  line L20 (-24.7495, 46) -> (-24.7495, 47)
  line L21 (28.2005, 46) -> (28.2005, 47)
  line L22 (-28.7495, -46) -> (-27.3495, -46)
  line L23 (-27.3495, -47) -> (-27.3495, -46)
  line L24 (-27.7495, 20) -> (-27.7495, -46)
  line L25 (32.8005, -8) -> (30.8005, -8)
  line L26 (32.8005, -6) -> (32.8005, -8)
  line L27 (30.8005, -6) -> (32.8005, -6)
  line L28 (30.8005, -8) -> (30.8005, -6)
  line L29 (45.3026, 0) -> (0, 0)
  line L30 (30.8005, 6) -> (32.8005, 6)
  line L31 (32.8005, 6) -> (32.8005, 8)
  line L32 (30.8005, 8) -> (30.8005, 6)
  line L33 (32.8005, 8) -> (30.8005, 8)
  line L34 (-30.3495, -30) -> (-29.3495, -30)
  line L35 (-30.3495, -35.7) -> (-30.3495, -30)
  line L36 (-29.3495, -35.7) -> (-30.3495, -35.7)
  line L37 (-29.3495, -30) -> (-29.3495, -35.7)
  line L38 (-44.1093, 0) -> (0, 0)
  line L39 (-29.3495, 7) -> (-30.3495, 7)
  line L40 (-29.3495, 12.7) -> (-29.3495, 7)
  line L41 (-30.3495, 12.7) -> (-29.3495, 12.7)
  line L42 (-30.3495, 7) -> (-30.3495, 12.7)
  line L43 (-29.3495, 34.8) -> (-30.3495, 34.8)
  line L44 (-29.3495, 40.5) -> (-29.3495, 34.8)
  line L45 (-30.3495, 40.5) -> (-29.3495, 40.5)
  line L46 (-30.3495, 34.8) -> (-30.3495, 40.5)
  line L47 (32.8005, 6) -> (32.8005, -6)
  line L48 (-29.3495, -38.4757) -> (-29.3495, 50.9862)
  line L49 (-27.7495, -47) -> (-27.7495, -46)
  line L50 (-27.3495, 40.5) -> (-29.3495, 40.5)
  line L51 (-27.3495, 34.8) -> (-29.3495, 34.8)
  line L52 (-28.7495, 12.7) -> (-29.3495, 12.7)
  line L53 (-28.7495, 7) -> (-29.3495, 7)
  line L54 (-28.7495, -30) -> (-29.3495, -30)
  line L55 (-28.7495, -35.7) -> (-29.3495, -35.7)
  arc A1 centre (-31.9995, 0) radius 2.5831 clockwise from (-31.3495, 2.5) to (-31.3495, -2.5)
  point P25 (-28.7495, 20)
  point P26 (-27.3495, 20)
  point P27 (-28.7495, 45)
  point P28 (-27.3495, 45)
  point P29 (-24.7495, 47)
  point P30 (-24.7495, 46)
  point P31 (28.2005, 47)
  point P32 (28.2005, 46)
  point P17 (-27.3495, -46)
  point P33 (-27.3495, -46)
  point P34 (-28.7495, -46)
  point P36 (-27.3495, -47)
  point P37 (-27.7495, -46)
  point P38 (-27.7495, 20)
  point P1 (0, 0)
  point P43 (0, 0)
  point P39 (30.8005, -8)
  point P48 (30.8005, 8)
  point P40 (32.8005, -8)
  point P47 (32.8005, 8)
  point P41 (32.8005, -6)
  point P45 (32.8005, 6)
  point P42 (30.8005, -6)
  point P46 (30.8005, 6)
  point P53 (0, 0)
  point P61 (-29.3495, 40.5)
  point P49 (-29.3495, -30)
  point P59 (-30.3495, 34.8)
  point P66 (-30.3495, 34.8)
  point P62 (-30.3495, 40.5)
  point P67 (-30.3495, 40.5)
  point P55 (-30.3495, 7)
  point P65 (-30.3495, 7)
  point P58 (-30.3495, 12.7)
  point P68 (-30.3495, 12.7)
  point P57 (-29.3495, 12.7)
  point P35 (-27.3495, -46)
  point P69 (-27.7495, -47)
  point P70 (-27.3495, 40.5)
  point P71 (-27.3495, 34.8)
  point P72 (-28.7495, 12.7)
  point P73 (-28.7495, 7)
  point P74 (-28.7495, -30)
  point P75 (-28.7495, -35.7)
  point P52 (-29.3495, -35.7)
  point P56 (-29.3495, 7)
  point P60 (-29.3495, 34.8)
  point P51 (-30.3495, -35.7)
  horizontal L10
  vertical L11
  horizontal L12
  vertical L13
  coincident L11 P25
  coincident L14 P26
  perpendicular L14 L18
  coincident L11 P27
  coincident L14 P28
  perpendicular L14 L19
  coincident L12 P29
  coincident L15 P30
  perpendicular L15 L20
  coincident L12 P31
  coincident L15 P32
  perpendicular L15 L21
  coincident P17 P33
  coincident L11 P34
  perpendicular L11 L22
  coincident L10 P36
  perpendicular L10 L23
  coincident L22 P37
  coincident L18 P38
  perpendicular L18 L24
  horizontal L25
  vertical L26
  horizontal L27
  vertical L28
  coincident P1 P43
  horizontal L29
  symmetric P39 L29 P48
  symmetric P40 L29 P47
  symmetric P41 L29 P45
  symmetric P42 L29 P46
  horizontal L34
  vertical L35
  horizontal L36
  vertical L37
  coincident P1 P53
  perpendicular L14 L38
  horizontal L39
  vertical L40
  horizontal L41
  vertical L42
  horizontal L43
  vertical L44
  horizontal L45
  vertical L46
  perpendicular L38 L48
  coincident P61 L48
  coincident P49 L48
  coincident P59 P66
  coincident P62 P67
  coincident P55 P65
  coincident P58 P68
  coincident P57 L48
  coincident P33 P35
  coincident L10 P69
  perpendicular L10 L49
  coincident L14 P70
  perpendicular L14 L50
  coincident L14 P71
  perpendicular L14 L51
  coincident L11 P72
  perpendicular L11 L52
  coincident L11 P73
  perpendicular L11 L53
  coincident L11 P74
  perpendicular L11 L54
  coincident L11 P75
  perpendicular L11 L55
  dimension "d124" distance L6 L10 = 2
  dimension "d125" distance L7 L13 = 1
  dimension "d126" distance L8 L12 = 2 (= "d124")
  dimension "d127" distance L9 L11 = 2.6
  dimension "d142" distance L12 L18 = 27
  dimension "d143" distance L12 L19 = 2
  dimension "d144" distance L11 L20 = 4
  dimension "d145" distance L13 L21 = 4.1
  dimension "d146" distance L4 L24 = 0.4
  dimension "d147" distance L7 L26 = 0.5
  dimension "d148" distance P39 P40 = 2
  dimension "d149" distance P39 P42 = 2
  dimension "d151" distance L25 L33 = 16
  dimension "d152" distance P49 P52 = 5.7
  dimension "d154" distance L34 L38 = 30
  dimension "d155" distance P56 P57 = 5.7 (= "d152")
  dimension "d158" distance P60 P61 = 5.7 (= "d152")
  dimension "d159" distance L34 L39 = 37
  dimension "d160" distance L39 L43 = 27.8
  dimension "d184" distance P51 P52 = 1
  dimension "d185" distance L4 L48 = 2
  dimension "d187" distance P56 P65 = 1 (= "d184")
  dimension "d188" distance P60 P66 = 1 (= "d184")
extrude "Extrude2" new body sketch "Sketch2" profile of L13 L25 L26 L27 L28 L30 L31 L32 L33 along normal blind 6.5
extrude "Extrude3" add sketch "Sketch2" profile of L1 L4 L11 L12 L14 L15 L18 L19 L20 L21 L22 L24 L34 L35 L36 L37 L39 L40 L41 L42 L43 L44 L45 L46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 along normal blind 3
extrude "Extrude4" add sketch "Sketch2" profile of L1 L12 L15 L20 L21 along normal blind 3.3
extrude "Extrude5" add sketch "Sketch2" profile of L1 L2 L3 L4 L10 L12 L13 L14 L15 L16 L17 L18 L21 L22 L23 L24 L25 L27 L28 L30 L32 L33 L47 L49 along normal blind 1
sketch "Sketch4" plane through (0, 6, 0) normal (0, -1, 0) x axis (1, 0, 0)
  line L1 (-30.8005, 2) -> (-32.8005, 2)
  line L2 (-30.8005, 7.5) -> (-30.8005, 2)
  line L3 (-32.8005, 7.5) -> (-30.8005, 7.5)
  line L4 (-32.8005, 2) -> (-32.8005, 7.5)
  line L5 (-30.8005, 5.5) -> (-32.8005, 5.5)
  point P7 (-32.8005, 5.5)
  point P8 (-30.8005, 5.5)
  coincident L4 P7
  coincident L2 P8
  perpendicular L2 L5
  dimension "d172" distance L3 L5 = 2
extrude "Extrude7" add sketch "Sketch4" profile of L2 L3 L4 L5 to an object
sketch "Sketch5" plane through (30.3495, 0, 0) normal (1, 0, 0) x axis (0, 1, 0)
  line L1 (-2.4, 0) -> (-49, 0)
  line L2 (-2.4, 1) -> (-2.4, 0)
  line L3 (-34.815, 1) -> (-40.515, 1)
  line L4 (-7.015, 4) -> (-7.015, 1)
  line L5 (-40.515, 4) -> (-34.815, 4)
  line L6 (-12.715, 1) -> (-12.715, 4)
  line L7 (-34.815, 4) -> (-34.815, 1)
  line L8 (-40.515, 1) -> (-40.515, 4)
  line L9 (-49, 1) -> (-2.4, 1)
  line L10 (-49, 0) -> (-49, 1)
  line L11 (-34.815, 2.2) -> (-40.515, 2.2)
  line L12 (-7.015, 2.2) -> (-12.715, 2.2)
  line L13 (29.985, 4) -> (29.985, 1)
  line L14 (35.685, 4) -> (35.685, 1)
  line L15 (49, 0) -> (2.4, 0)
  line L16 (49, 1) -> (49, 0)
  line L17 (2.4, 1) -> (49, 1)
  line L18 (35.685, 4) -> (35.685, 1)
  line L19 (29.985, 4) -> (35.685, 4)
  line L20 (29.985, 1) -> (29.985, 4)
  line L21 (2.4, 0) -> (2.4, 1)
  line L22 (35.685, 2.2) -> (29.985, 2.2)
  line L23 (-7.015, 1) -> (-12.715, 1)
  line L24 (-12.715, 4) -> (-7.015, 4)
  line L25 (35.685, 1) -> (29.985, 1)
  line L26 (-34.8, 1) -> (-40.5, 1)
  line L27 (-34.8, 4) -> (-34.8, 1)
  line L28 (-40.5, 4) -> (-34.8, 4)
  line L29 (-40.5, 1) -> (-40.5, 4)
  point P14 (-40.515, 2.2)
  point P15 (-34.815, 2.2)
  point P16 (-12.715, 2.2)
  point P17 (-7.015, 2.2)
  point P30 (29.985, 2.2)
  point P31 (35.685, 2.2)
  coincident L8 P14
  coincident L7 P15
  perpendicular L7 L11
  coincident L6 P16
  coincident L4 P17
  perpendicular L4 L12
  coincident L13 P30
  coincident L14 P31
  perpendicular L14 L22
  dimension "d177" distance L19 L22 = 1.8 (= "d190")
  dimension "d190" distance L5 L11 = 1.8
  dimension "d191" distance L12 L24 = 1.8 (= "d190")
fillet "Fillet1" radius 2.5
fillet "Fillet2" radius 1.5
extrude "Extrude10" add sketch "Sketch5" profile of L4 L5 L6 L7 L11 L12 L13 L14 L18 L19 L20 L22 L24 L28 L29 along normal blind 3
fillet "Fillet3" radius 2.25
sketch "Sketch8" plane through (0, -40.5, 0) normal (0, -1, 0) x axis (1, 0, 0)
  line L1 (30.3495, 1) -> (27.3495, 1)
  line L2 (30.3495, 2.2) -> (30.3495, 1)
  line L3 (33.3495, 2.2) -> (30.3495, 2.2)
  line L4 (33.3495, 4) -> (33.3495, 2.2)
  line L5 (27.3495, 4) -> (33.3495, 4)
  line L6 (31.5495, 2.2) -> (33.3495, 4)
  line L7 (27.3495, 1) -> (27.3495, 4)
  point P6 (33.3495, 4)
  point P8 (33.3495, 4)
  point P9 (31.5495, 2.2)
  coincident P6 P8
  coincident L3 P9
  dimension "d199" angle L5 L6 = 135
extrude "Extrude12" cut sketch "Sketch8" profile of L3 L4 L6 no distance stored
base_mesh_feature "Base Mesh Feature1"
sketch "Sketch1" plane through (0, 0, 0) normal (0, 0, 1) x axis (1, 0, 0)
  line L1 (0, 58.1692) -> (0, 0)
  line L2 (50.015, 0) -> (0, 0)
  line L3 (30.5, 48) -> (-30.5, 48)
  line L4 (30.5, -48) -> (30.5, 48)
  line L5 (-30.5, -48) -> (30.5, -48)
  line L6 (-30.5, 48) -> (-30.5, -48)
  line L7 (28.325, 46) -> (-28.325, 46)
  line L8 (28.325, -46) -> (28.325, 46)
  line L9 (-28.325, -46) -> (28.325, -46)
  line L10 (-28.325, 46) -> (-28.325, -46)
  line L11 (27.325, -45) -> (27.325, 45)
  line L12 (-27.325, -45) -> (27.325, -45)
  line L13 (-27.325, 45) -> (-27.325, -45)
  line L14 (27.325, 45) -> (-27.325, 45)
  point P1 (0, 0)
  point P2 (0, 0)
  point P4 (0, 0)
  point P6 (-30.5, 48)
  point P7 (30.5, 48)
  point P8 (30.5, -48)
  point P10 (-28.325, 46)
  point P11 (28.325, 46)
  coincident P1 P2
  vertical L1
  coincident P1 P4
  perpendicular L1 L2
  horizontal L3
  vertical L4
  horizontal L5
  vertical L6
  symmetric L2 L3 L5
  horizontal L7
  vertical L8
  horizontal L9
  vertical L10
  symmetric L1 L8 L10
  dimension "d201" distance P6 P7 = 61
  dimension "d202" distance P7 P8 = 96
  dimension "d216" distance L3 L7 = 2
  dimension "d217" distance L5 L9 = 2 (= "d216")
  dimension "d218" distance P10 P11 = 56.65
  dimension "d219" = 1
extrude "Extrude1" new body sketch "Sketch1" profile of L3 L4 L5 L6 along normal blind 1.5 bodies "back_pack_part2"
extrude "Extrude4" add sketch "Sketch1" profile of L3 L4 L5 L6 L7 L8 L9 L10 L14 L13 L12 L11 along normal blind 5.5
extrude "Extrude5" add sketch "Sketch1" profile of L7 L8 L9 L10 L14 L13 L12 L11 along normal blind 6.5
fillet "Fillet2" radius 2
joint "Assemble1" alignAngle 0 alignOffsetX 0 alignOffsetY 0 alignOffsetZ 0
extrude "Extrude15" add of existing geometry blind 0.5
sketch "Sketch9" plane through (0, 0, 2) normal (0, 0, 1) x axis (-1, 0, 0)
  line L1 (30.8005, -47) -> (-25.8787, -47)
  line L2 (32.3005, -10.5) -> (32.3005, -45.5)
  line L3 (30.8005, -10.5) -> (32.3005, -10.5)
  line L4 (30.8005, -6) -> (30.8005, -10.5)
  line L5 (32.8005, -6) -> (30.8005, -6)
  line L6 (32.8005, 6) -> (32.8005, -6)
  line L7 (30.8005, 6) -> (32.8005, 6)
  line L8 (30.8005, 10.5) -> (30.8005, 6)
  line L9 (32.3005, 10.5) -> (30.8005, 10.5)
  line L10 (32.3005, 45.5) -> (32.3005, 10.5)
  line L11 (28.2005, 47) -> (30.8005, 47)
  line L12 (28.2005, 46) -> (28.2005, 47)
  line L13 (29.3005, 46) -> (28.2005, 46)
  line L14 (29.3005, -46) -> (29.3005, 46)
  line L15 (-27.3495, -46) -> (29.3005, -46)
  line L16 (-27.3495, 20) -> (-27.3495, -46)
  line L17 (-27.7495, 20) -> (-27.3495, 20)
  line L18 (-27.7495, -46) -> (-27.7495, 20)
  line L19 (29.3005, -47) -> (29.3005, -46)
  line L20 (-27.7495, -46) -> (-27.3495, -46)
  arc A1 centre (-25.8787, -44.75) radius 2.25 clockwise from (-25.8787, -47) to (-27.7495, -46)
  arc A2 centre (30.8005, -45.5) radius 1.5 clockwise from (32.3005, -45.5) to (30.8005, -47)
  arc A3 centre (30.8005, 45.5) radius 1.5 clockwise from (30.8005, 47) to (32.3005, 45.5)
  point P22 (29.3005, -46)
  point P26 (29.3005, -46)
  point P27 (29.3005, -47)
  point P23 (-27.3495, -46)
  point P28 (-27.3495, -46)
  point P2 (-27.7495, -46)
  point P29 (-27.7495, -46)
  coincident P22 P26
  coincident L1 P27
  perpendicular L1 L19
  coincident P23 P28
  coincident P2 P29
extrude "Extrude13" add sketch "Sketch9" profile of A1 L1 L15 L19 L20 along normal blind 1
extrude "Extrude14" add of existing geometry blind 1
fillet "Fillet5" radius 3
fillet "Fillet7" radius 0.7
base_mesh_feature "Base Mesh Feature1"
sketch "Sketch1" plane through (0, 0, 0) normal (0, 0, 1) x axis (1, 0, 0)
  line L1 (31.3495, 49) -> (-33.3005, 49)
  line L2 (31.3495, -49) -> (31.3495, 49)
  line L3 (-33.3005, -49) -> (31.3495, -49)
  line L4 (-33.3005, 49) -> (-33.3005, -49)
  line L5 (0, 55.7908) -> (0, 0)
  line L6 (49.8312, 0) -> (0, 0)
  line L7 (27.3495, 46) -> (-29.3005, 46)
  line L8 (27.3495, -46) -> (27.3495, 46)
  line L9 (-29.3005, -46) -> (27.3495, -46)
  line L10 (-29.3005, 46) -> (-29.3005, -46)
  arc A1 centre (31.9995, 0) radius 2.5831 clockwise from (31.3495, -2.5) to (31.3495, 2.5)
  point P1 (0, 0)
  point P6 (0, 0)
  point P8 (0, 0)
  point P11 (31.3495, -2.5)
  point P10 (31.3495, 2.5)
  point P12 (31.9995, 0)
  point P2 (-33.3005, 49)
  point P3 (31.3495, 49)
  horizontal L1
  vertical L2
  horizontal L3
  vertical L4
  coincident P1 P6
  perpendicular L1 L5
  coincident P1 P8
  perpendicular L5 L6
  symmetric L1 L3 L6
  coincident L2 P11
  coincident L2 P10
  symmetric L6 P10 P11
  horizontal L7
  vertical L8
  horizontal L9
  vertical L10
  dimension "d114_1" distance L1 L3 = 98
  dimension "d115_1" distance P10 P11 = 5
  dimension "d116_1" distance L2 P12 = 0.65
  dimension "d117_1" distance L1 L7 = 3
  dimension "d118_1" distance L3 L9 = 3 (= "d117_1")
  dimension "d119_1" distance L2 L8 = 4
  dimension "d120_1" distance L4 L10 = 4
  dimension "d198_1" distance P2 P3 = 64.65
extrude "Extrude1" new body sketch "Sketch1" profile of L1 L2 L3 L4 A1 L7 L8 L9 L10 along normal blind 1 named "d122_1"
sketch "Sketch2" plane through (0, 0, 1) normal (0, 0, 1) x axis (-1, 0, 0)
  line L1 (29.3005, 46) -> (-27.3495, 46)
  line L2 (29.3005, -46) -> (29.3005, 46)
  line L3 (-27.3495, -46) -> (29.3005, -46)
  line L4 (-27.3495, 46) -> (-27.3495, -46)
  line L5 (-31.3495, -49) -> (-31.3495, -2.5)
  line L6 (33.3005, -49) -> (-31.3495, -49)
  line L7 (33.3005, 49) -> (33.3005, -49)
  line L8 (-31.3495, 49) -> (33.3005, 49)
  line L9 (-31.3495, 2.5) -> (-31.3495, 49)
  line L10 (-28.7495, -47) -> (32.3005, -47)
  line L11 (-28.7495, 47) -> (-28.7495, -47)
  line L12 (32.3005, 47) -> (-28.7495, 47)
  line L13 (32.3005, -47) -> (32.3005, 47)
  line L14 (-27.3495, 46) -> (-27.3495, -46)
  line L15 (29.3005, 46) -> (-27.3495, 46)
  line L16 (29.3005, -46) -> (29.3005, 46)
  line L17 (-27.3495, -46) -> (29.3005, -46)
  line L18 (-27.3495, 20) -> (-28.7495, 20)
  line L19 (-27.3495, 45) -> (-28.7495, 45)
  line L20 (-24.7495, 46) -> (-24.7495, 47)
  line L21 (28.2005, 46) -> (28.2005, 47)
  line L22 (-28.7495, -46) -> (-27.3495, -46)
  line L23 (-27.3495, -47) -> (-27.3495, -46)
  line L24 (-27.7495, 20) -> (-27.7495, -46)
  line L25 (32.8005, -8) -> (30.8005, -8)
  line L26 (32.8005, -6) -> (32.8005, -8)
  line L27 (30.8005, -6) -> (32.8005, -6)
  line L28 (30.8005, -8) -> (30.8005, -6)
  line L29 (45.3026, 0) -> (0, 0)
  line L30 (30.8005, 6) -> (32.8005, 6)
  line L31 (32.8005, 6) -> (32.8005, 8)
  line L32 (30.8005, 8) -> (30.8005, 6)
  line L33 (32.8005, 8) -> (30.8005, 8)
  line L34 (-30.3495, -30) -> (-29.3495, -30)
  line L35 (-30.3495, -35.7) -> (-30.3495, -30)
  line L36 (-29.3495, -35.7) -> (-30.3495, -35.7)
  line L37 (-29.3495, -30) -> (-29.3495, -35.7)
  line L38 (-44.1093, 0) -> (0, 0)
  line L39 (-29.3495, 7) -> (-30.3495, 7)
  line L40 (-29.3495, 12.7) -> (-29.3495, 7)
  line L41 (-30.3495, 12.7) -> (-29.3495, 12.7)
  line L42 (-30.3495, 7) -> (-30.3495, 12.7)
  line L43 (-29.3495, 34.8) -> (-30.3495, 34.8)
  line L44 (-29.3495, 40.5) -> (-29.3495, 34.8)
  line L45 (-30.3495, 40.5) -> (-29.3495, 40.5)
  line L46 (-30.3495, 34.8) -> (-30.3495, 40.5)
  line L47 (32.8005, 6) -> (32.8005, -6)
  line L48 (-29.3495, -38.4757) -> (-29.3495, 50.9862)
  line L49 (-27.7495, -47) -> (-27.7495, -46)
  line L50 (-27.3495, 40.5) -> (-29.3495, 40.5)
  line L51 (-27.3495, 34.8) -> (-29.3495, 34.8)
  line L52 (-28.7495, 12.7) -> (-29.3495, 12.7)
  line L53 (-28.7495, 7) -> (-29.3495, 7)
  line L54 (-28.7495, -30) -> (-29.3495, -30)
  line L55 (-28.7495, -35.7) -> (-29.3495, -35.7)
  arc A1 centre (-31.9995, 0) radius 2.5831 clockwise from (-31.3495, 2.5) to (-31.3495, -2.5)
  point P25 (-28.7495, 20)
  point P26 (-27.3495, 20)
  point P27 (-28.7495, 45)
  point P28 (-27.3495, 45)
  point P29 (-24.7495, 47)
  point P30 (-24.7495, 46)
  point P31 (28.2005, 47)
  point P32 (28.2005, 46)
  point P17 (-27.3495, -46)
  point P33 (-27.3495, -46)
  point P34 (-28.7495, -46)
  point P36 (-27.3495, -47)
  point P37 (-27.7495, -46)
  point P38 (-27.7495, 20)
  point P1 (0, 0)
  point P43 (0, 0)
  point P39 (30.8005, -8)
  point P48 (30.8005, 8)
  point P40 (32.8005, -8)
  point P47 (32.8005, 8)
  point P41 (32.8005, -6)
  point P45 (32.8005, 6)
  point P42 (30.8005, -6)
  point P46 (30.8005, 6)
  point P53 (0, 0)
  point P61 (-29.3495, 40.5)
  point P49 (-29.3495, -30)
  point P59 (-30.3495, 34.8)
  point P66 (-30.3495, 34.8)
  point P62 (-30.3495, 40.5)
  point P67 (-30.3495, 40.5)
  point P55 (-30.3495, 7)
  point P65 (-30.3495, 7)
  point P58 (-30.3495, 12.7)
  point P68 (-30.3495, 12.7)
  point P57 (-29.3495, 12.7)
  point P35 (-27.3495, -46)
  point P69 (-27.7495, -47)
  point P70 (-27.3495, 40.5)
  point P71 (-27.3495, 34.8)
  point P72 (-28.7495, 12.7)
  point P73 (-28.7495, 7)
  point P74 (-28.7495, -30)
  point P75 (-28.7495, -35.7)
  point P52 (-29.3495, -35.7)
  point P56 (-29.3495, 7)
  point P60 (-29.3495, 34.8)
  point P51 (-30.3495, -35.7)
  horizontal L10
  vertical L11
  horizontal L12
  vertical L13
  coincident L11 P25
  coincident L14 P26
  perpendicular L14 L18
  coincident L11 P27
  coincident L14 P28
  perpendicular L14 L19
  coincident L12 P29
  coincident L15 P30
  perpendicular L15 L20
  coincident L12 P31
  coincident L15 P32
  perpendicular L15 L21
  coincident P17 P33
  coincident L11 P34
  perpendicular L11 L22
  coincident L10 P36
  perpendicular L10 L23
  coincident L22 P37
  coincident L18 P38
  perpendicular L18 L24
  horizontal L25
  vertical L26
  horizontal L27
  vertical L28
  coincident P1 P43
  horizontal L29
  symmetric P39 L29 P48
  symmetric P40 L29 P47
  symmetric P41 L29 P45
  symmetric P42 L29 P46
  horizontal L34
  vertical L35
  horizontal L36
  vertical L37
  coincident P1 P53
  perpendicular L14 L38
  horizontal L39
  vertical L40
  horizontal L41
  vertical L42
  horizontal L43
  vertical L44
  horizontal L45
  vertical L46
  perpendicular L38 L48
  coincident P61 L48
  coincident P49 L48
  coincident P59 P66
  coincident P62 P67
  coincident P55 P65
  coincident P58 P68
  coincident P57 L48
  coincident P33 P35
  coincident L10 P69
  perpendicular L10 L49
  coincident L14 P70
  perpendicular L14 L50
  coincident L14 P71
  perpendicular L14 L51
  coincident L11 P72
  perpendicular L11 L52
  coincident L11 P73
  perpendicular L11 L53
  coincident L11 P74
  perpendicular L11 L54
  coincident L11 P75
  perpendicular L11 L55
  dimension "d124_1" distance L6 L10 = 2
  dimension "d125_1" distance L7 L13 = 1
  dimension "d126_1" distance L8 L12 = 2 (= "d124_1")
  dimension "d127_1" distance L9 L11 = 2.6
  dimension "d142_1" distance L12 L18 = 27
  dimension "d143_1" distance L12 L19 = 2
  dimension "d144_1" distance L11 L20 = 4
  dimension "d145_1" distance L13 L21 = 4.1
  dimension "d146_1" distance L4 L24 = 0.4
  dimension "d147_1" distance L7 L26 = 0.5
  dimension "d148_1" distance P39 P40 = 2
  dimension "d149_1" distance P39 P42 = 2
  dimension "d151_1" distance L25 L33 = 16
  dimension "d152_1" distance P49 P52 = 5.7
  dimension "d154_1" distance L34 L38 = 30
  dimension "d155_1" distance P56 P57 = 5.7 (= "d152_1")
  dimension "d158_1" distance P60 P61 = 5.7 (= "d152_1")
  dimension "d159_1" distance L34 L39 = 37
  dimension "d160_1" distance L39 L43 = 27.8
  dimension "d184_1" distance P51 P52 = 1
  dimension "d185_1" distance L4 L48 = 2
  dimension "d187_1" distance P56 P65 = 1 (= "d184_1")
  dimension "d188_1" distance P60 P66 = 1 (= "d184_1")
extrude "Extrude2" new body sketch "Sketch2" profile of L13 L25 L26 L27 L28 L30 L31 L32 L33 along normal blind 6.5 named "d161_1"
extrude "Extrude3" add sketch "Sketch2" profile of L1 L4 L11 L12 L14 L15 L18 L19 L20 L21 L22 L24 L34 L35 L36 L37 L39 L40 L41 L42 L43 L44 L45 L46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 along normal blind 3 named "d163_1"
extrude "Extrude4" add sketch "Sketch2" profile of L1 L12 L15 L20 L21 along normal blind 3.3 named "d165_1"
extrude "Extrude5" add sketch "Sketch2" profile of L1 L2 L3 L4 L10 L12 L13 L14 L15 L16 L17 L18 L21 L22 L23 L24 L25 L27 L28 L30 L32 L33 L47 L49 along normal blind 1 named "d167_1"
sketch "Sketch4" plane through (0, 6, 0) normal (0, -1, 0) x axis (1, 0, 0)
  line L1 (-30.8005, 2) -> (-32.8005, 2)
  line L2 (-30.8005, 7.5) -> (-30.8005, 2)
  line L3 (-32.8005, 7.5) -> (-30.8005, 7.5)
  line L4 (-32.8005, 2) -> (-32.8005, 7.5)
  line L5 (-30.8005, 5.5) -> (-32.8005, 5.5)
  point P7 (-32.8005, 5.5)
  point P8 (-30.8005, 5.5)
  coincident L4 P7
  coincident L2 P8
  perpendicular L2 L5
  dimension "d172_1" distance L3 L5 = 2
extrude "Extrude7" add sketch "Sketch4" profile of L2 L3 L4 L5 to an object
